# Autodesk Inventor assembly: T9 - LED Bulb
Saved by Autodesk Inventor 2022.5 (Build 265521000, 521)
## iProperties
Created: 2024-07
Part Number: T9 - LED Bulb
Document SubType Name: Assembly
Designer: AdminForWorker
Title: T9 - LED Bulb
Author: AdminForWorker
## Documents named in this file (3)
- c:\worker\convert-fusion-r03-cosv3\tmp\job-1\157\temp\files\32f11fbc-73c2-4b73-b173-800995eb16ca\T9 - LED Bulb.iam
- c:\worker\convert-fusion-r03-cosv3\tmp\job-1\157\temp\files\32f11fbc-73c2-4b73-b173-800995eb16ca\T9.ipt
- c:\worker\convert-fusion-r03-cosv3\tmp\job-1\157\temp\files\32f11fbc-73c2-4b73-b173-800995eb16ca\E26 Base.ipt
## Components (2 placed, 2 different names)
1. T9:1
2. E26 Base:1
